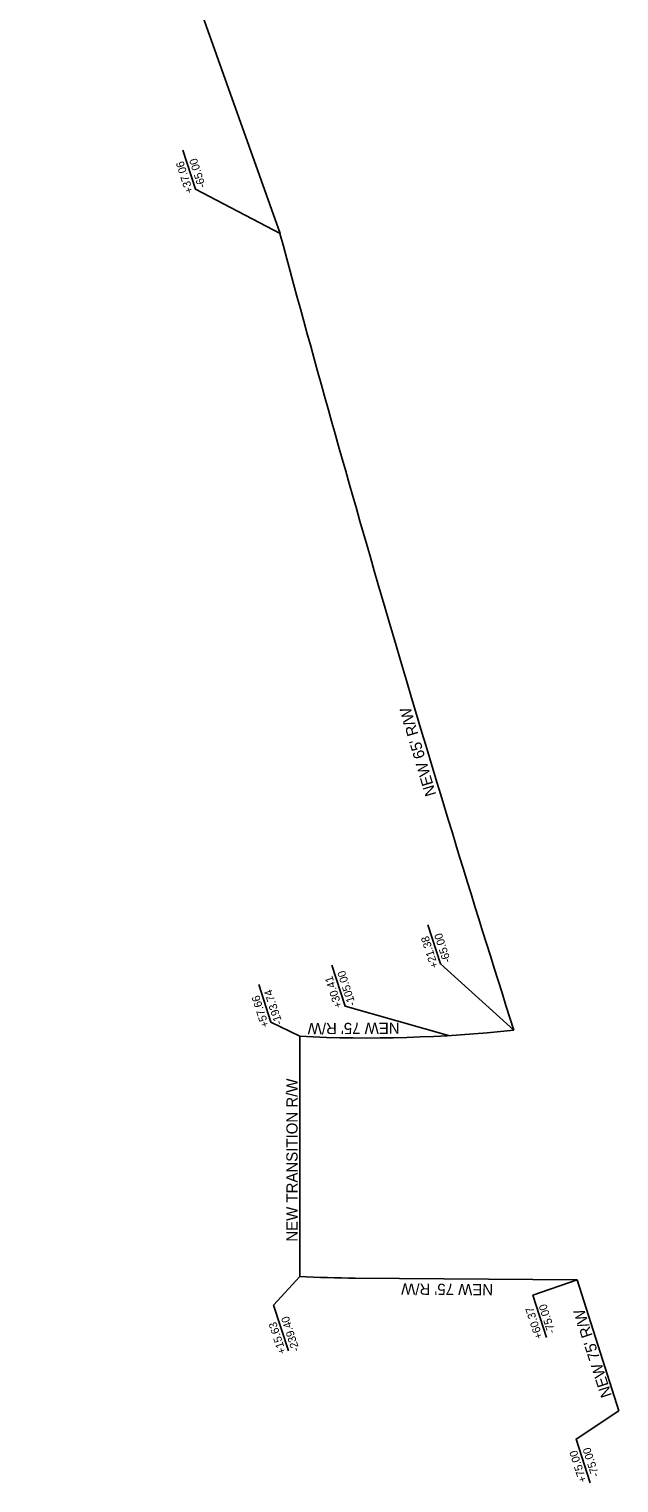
# Model space of a CAD drawing. Extents: x 2003184 to 2010449, y 855784 to 861212.
# Drawn here: x 2004768 to 2005136, y 856362 to 857270 of the extents above; entities that cross this region are included whole.
import ezdxf

# ---------------------------------------------------------------- set-up
doc = ezdxf.new("R2010")
doc.units = 0
doc.layers.add('RD_PD_RW', color=7, linetype='Continuous')
doc.layers.add('RD_PD_RW_TX', color=7, linetype='Continuous')

msp = doc.modelspace()

# ---------------------------------------------------------------- linework, layer by layer
at = {"layer": 'RD_PD_RW'}
for p, q in [((2004924.58, 857142.67), (2004767.78, 857584.21)), ((2004936.9, 856641.25), (2004936.9, 856491.09)), ((2005110.17, 856489.1), (2004971.62, 856490.21)), ((2005136.37, 856407.32), (2005110.17, 856489.1))]:
    msp.add_line(p, q, dxfattribs=at)
for centre, radius, start, end in [((2016051.98, 860140.53), 11524.16, 195.07818, 197.656576), ((2004979.52, 857482.36), 842.19, 267.09934, 276.21614), ((2004979.52, 857482.36), 992.19, 267.53816, 269.54383)]:
    msp.add_arc(centre, radius, start, end, dxfattribs=at)
at = {"layer": 'RD_PD_RW_TX'}
for points in [[(2004863.9, 857194.79), (2004871.78, 857170.43), (2004924.58, 857142.67)], [(2005017.01, 856710.79), (2005024.88, 856686.42), (2005070.71, 856645.13)], [(2004956.99, 856685.6), (2004965.22, 856660.1), (2005029.83, 856641.68)], [(2004911.26, 856673.69), (2004918.87, 856650.15), (2004936.9, 856641.25)], [(2004929.83, 856444.72), (2004920.59, 856473.33), (2004936.9, 856491.09)], [(2005091.2, 856453.09), (2005082.66, 856479.51), (2005110.17, 856489.1)], [(2005118.44, 856362.24), (2005109.6, 856389.59), (2005136.37, 856407.32)]]:
    msp.add_lwpolyline(points, dxfattribs=at)

# ---------------------------------------------------------------- texts
for s, height, rotation, p in [('-65.00', 5, 107.9072, (2004878.32, 857172.13)), ('+37.06', 5, 107.9072, (2004870.48, 857168.75)), ("NEW 65' R/W", 7, 106.50399, (2005022.29, 856792.34)), ('+21.38', 5, 107.9072, (2005023.6, 856684.7)), ('-65.00', 5, 107.9072, (2005031.43, 856688.12)), ('-105.00', 5, 107.9072, (2004971.98, 856661.14)), ('+30.41', 5, 107.9072, (2004963.51, 856659.73)), ('+57.66', 5, 107.9072, (2004917.84, 856647.64)), ('-193.74', 5, 107.9072, (2004926.23, 856649.31)), ("NEW 75' R/W", 7, 180.32118, (2004999.28, 856649.82)), ('NEW TRANSITION R/W', 7, 90, (2004935.55, 856512.94)), ("NEW 75' R/W", 7, 179.54383, (2005057.76, 856486.4)), ('-75.00', 5, 107.9072, (2005096.71, 856456.42)), ('+15.63', 5, 107.9072, (2004928.47, 856443.59)), ('-239.40', 5, 107.9072, (2004936.88, 856445.22)), ('+60.37', 5, 107.9072, (2005088.87, 856453.04)), ("NEW 75' R/W", 7, 107.90874, (2005132.1, 856416.87)), ('+75.00', 5, 107.9072, (2005116.35, 856363.4)), ('-75.00', 5, 107.9072, (2005124.17, 856366.82))]:
    msp.add_text(s, height=height, rotation=rotation, dxfattribs=at).set_placement(p)

doc.saveas('drawing.dxf')
